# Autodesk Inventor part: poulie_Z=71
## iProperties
Shininess: 64.0
Length Units: 11269
Angle Units: 11279
Time Units: 11290
Mass Units: 11283
Length Display Precision: 3
Angle Display Precision: 2
Compacted: True
Part Number: poulie_Z=71
Document SubType Name: Modeling
Created: 2004-05
Material: Par défaut
Designer: David
Density: 0.0
Volumn: 0.0
Area: 0.0
PropertySet Name: Model Information
Control State: 0
Master: False
Checked Out: False
Author: David
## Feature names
1. Extrusion1
2. Extrusion3
3. Congé4 [Fillet]
4. Réseau circulaire3 [Circular Pattern]
5. Extrusion4
6. Réseau circulaire4 [Circular Pattern]
7. Perçage1 [Hole]
8. Extrusion5
9. Symétrie1 [Mirror]
10. Extrusion6
11. Symétrie2 [Mirror]
12. Extrusion7
13. Réseau circulaire5 [Circular Pattern]
14. Extrusion8
15. Extrusion9
16. Réseau circulaire6 [Circular Pattern]
